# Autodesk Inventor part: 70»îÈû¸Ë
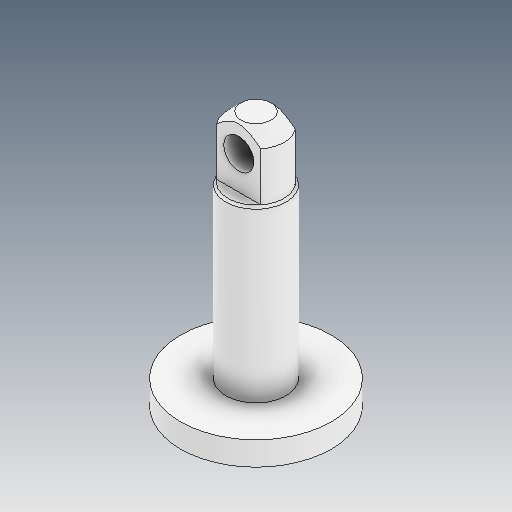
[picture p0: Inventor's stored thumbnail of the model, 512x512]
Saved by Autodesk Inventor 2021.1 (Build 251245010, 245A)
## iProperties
Created: 2021-05
Part Number: 70»îÈû¸Ë
Material: Ogólny
Document SubType Name: Modeling
Designer: user
Density: 1 g/cm^3
Appearance: Domyślna
Author: user
Revision Number: ÈÎºÎ
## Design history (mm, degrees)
feature "ÊäÈë1"
node "Bryła1"
